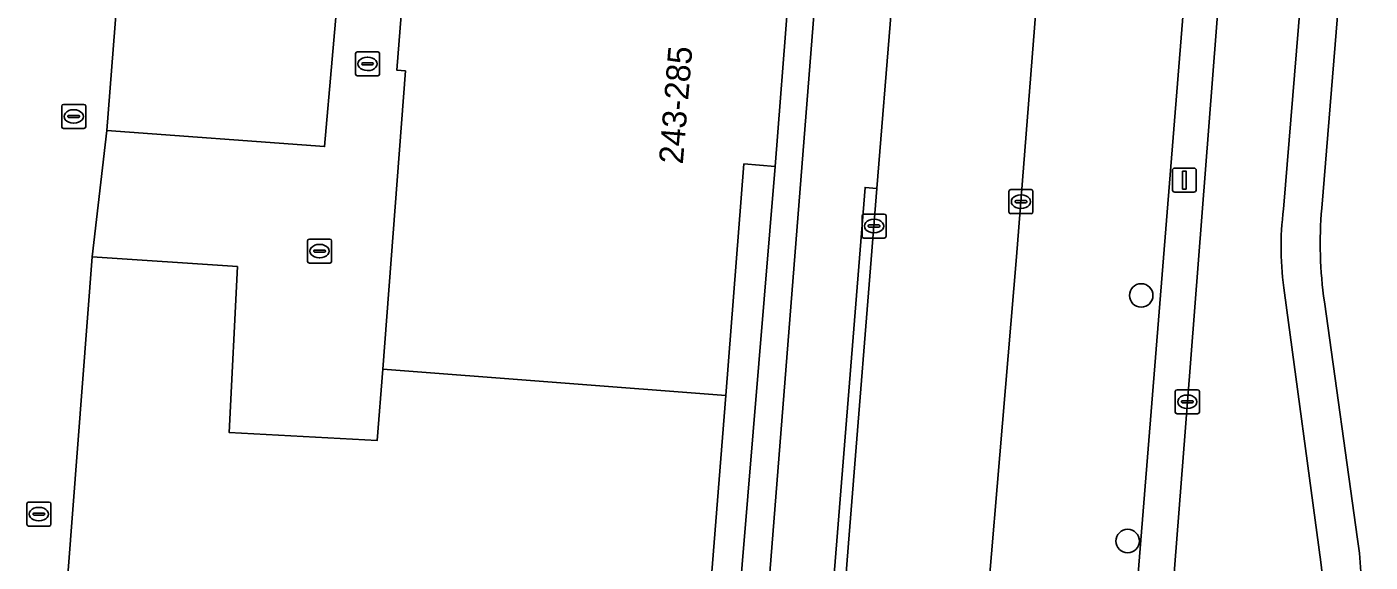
# Model space of a CAD drawing. Extents: x 160856 to 161310, y 384024 to 384878.
# Drawn here: x 161172 to 161227.9, y 384190.3 to 384212.6 of the extents above; entities that cross this region are included whole.
import ezdxf

# ---------------------------------------------------------------- set-up
doc = ezdxf.new("R2010")
doc.units = 0
for name, color, linetype in [('IMGEO_Berm_groen', 7, 'Continuous'), ('IMGEO_Boom', 7, 'Continuous'), ('IMGEO_Kolk', 7, 'Continuous'), ('IMGEO_Lichtmast', 7, 'Continuous'), ('IMGEO_Pand', 7, 'Continuous'), ('IMGEO_Pand_nummerreeks', 7, 'Continuous'), ('IMGEO_Parkeervlak_open', 7, 'Continuous'), ('IMGEO_Rijbaan_lokaal_gesloten', 7, 'Continuous'), ('IMGEO_Rijbaan_lokaal_open', 7, 'Continuous'), ('IMGEO_Voetpad_open', 7, 'Continuous')]:
    doc.layers.add(name, color=color, linetype=linetype)

msp = doc.modelspace()

# ---------------------------------------------------------------- linework, layer by layer
at = {"layer": 'IMGEO_Berm_groen'}
for points in [[(161229.529, 384268.467), (161229.449, 384267.686), (161229.325, 384266.219), (161224.3, 384204.981)], [(161225.892, 384205.014), (161231.046, 384268.295)], [(161219.187, 384267.539), (161224.271, 384267.23), (161224.48, 384267.204), (161221.069, 384224.897), (161220.682, 384220.094), (161216.321, 384165.759), (161215.782, 384159.058), (161212.885, 384159.261), (161212.995, 384161.563), (161210.036, 384161.719), (161209.719, 384161.736), (161209.242, 384156.268), (161209.155, 384155.272), (161209.068, 384154.275), (161209.373, 384154.297), (161209.267, 384152.43)], [(161218.789, 384177.498), (161220.294, 384196.951), (161221.806, 384216.321), (161223.443, 384236.712), (161224.98, 384255.032), (161225.162, 384257.276)], [(161224.34, 384201.487), (161225.848, 384190.269)], [(161227.386, 384191.221), (161226.005, 384201.112)]]:
    msp.add_lwpolyline(points, dxfattribs=at)
for centre, radius, start, end in [((161236.704, 384203.376), 12.507, 172.6261, 188.6857), ((161242.383, 384203.539), 16.557, 174.8888, 188.4288), ((161213.892, 384189.175), 13.648, 355.6, 8.6217), ((161207.617, 384187.652), 18.417, 356.4732, 8.1691)]:
    msp.add_arc(centre, radius, start, end, dxfattribs=at)
at = {"layer": 'IMGEO_Boom'}
for centre in [(161218.373, 384201.382), (161217.808, 384191.148)]:
    msp.add_circle(centre, 0.489, dxfattribs=at)
at = {"layer": 'IMGEO_Kolk'}
for p, q in [((161185.651, 384210.605), (161185.651, 384211.457)), ((161185.726, 384211.531), (161186.578, 384211.531)), ((161186.139, 384211.311), (161186.164, 384211.311)), ((161186.652, 384211.457), (161186.652, 384210.605)), ((161185.91, 384211.025), (161185.91, 384211.037)), ((161186.348, 384210.988), (161185.95, 384210.988)), ((161185.953, 384211.074), (161186.351, 384211.074)), ((161186.162, 384210.751), (161186.137, 384210.751)), ((161186.394, 384211.037), (161186.394, 384211.025)), ((161186.578, 384210.531), (161185.726, 384210.531)), ((161173.414, 384208.413), (161173.414, 384209.265)), ((161173.489, 384209.339), (161174.341, 384209.339)), ((161173.902, 384209.119), (161173.927, 384209.119)), ((161174.415, 384209.265), (161174.415, 384208.413)), ((161173.673, 384208.833), (161173.673, 384208.845)), ((161174.111, 384208.796), (161173.713, 384208.796)), ((161173.716, 384208.882), (161174.114, 384208.882)), ((161173.925, 384208.559), (161173.9, 384208.559)), ((161174.157, 384208.845), (161174.157, 384208.833)), ((161174.341, 384208.339), (161173.489, 384208.339)), ((161212.864, 384204.863), (161212.864, 384205.715)), ((161212.939, 384205.789), (161213.791, 384205.789)), ((161213.865, 384205.715), (161213.865, 384204.863)), ((161213.123, 384205.283), (161213.123, 384205.295)), ((161213.561, 384205.246), (161213.163, 384205.246)), ((161213.166, 384205.332), (161213.564, 384205.332)), ((161213.352, 384205.569), (161213.377, 384205.569)), ((161213.607, 384205.295), (161213.607, 384205.283)), ((161206.745, 384203.848), (161206.745, 384204.7)), ((161206.82, 384204.774), (161207.672, 384204.774)), ((161207.233, 384204.554), (161207.258, 384204.554)), ((161207.746, 384204.7), (161207.746, 384203.848)), ((161213.791, 384204.789), (161212.939, 384204.789)), ((161213.375, 384205.009), (161213.35, 384205.009)), ((161207.004, 384204.268), (161207.004, 384204.28)), ((161207.442, 384204.231), (161207.044, 384204.231)), ((161207.047, 384204.317), (161207.445, 384204.317)), ((161207.256, 384203.994), (161207.231, 384203.994)), ((161207.488, 384204.28), (161207.488, 384204.268)), ((161183.655, 384202.802), (161183.655, 384203.654)), ((161183.73, 384203.728), (161184.582, 384203.728)), ((161184.143, 384203.508), (161184.168, 384203.508)), ((161184.656, 384203.654), (161184.656, 384202.802)), ((161207.672, 384203.774), (161206.82, 384203.774)), ((161183.914, 384203.222), (161183.914, 384203.234)), ((161184.352, 384203.185), (161183.954, 384203.185)), ((161183.957, 384203.271), (161184.355, 384203.271)), ((161184.166, 384202.948), (161184.141, 384202.948)), ((161184.398, 384203.234), (161184.398, 384203.222)), ((161184.582, 384202.728), (161183.73, 384202.728)), ((161219.793, 384196.525), (161219.793, 384197.377)), ((161219.868, 384197.451), (161220.72, 384197.451)), ((161220.794, 384197.377), (161220.794, 384196.525)), ((161220.052, 384196.945), (161220.052, 384196.957)), ((161220.49, 384196.908), (161220.092, 384196.908)), ((161220.095, 384196.994), (161220.493, 384196.994)), ((161220.281, 384197.231), (161220.306, 384197.231)), ((161220.536, 384196.957), (161220.536, 384196.945)), ((161220.72, 384196.451), (161219.868, 384196.451)), ((161220.304, 384196.671), (161220.279, 384196.671)), ((161172.038, 384192.771), (161172.89, 384192.771)), ((161171.963, 384191.845), (161171.963, 384192.697)), ((161172.222, 384192.265), (161172.222, 384192.277)), ((161172.66, 384192.228), (161172.262, 384192.228)), ((161172.265, 384192.314), (161172.663, 384192.314)), ((161172.451, 384192.551), (161172.476, 384192.551)), ((161172.706, 384192.277), (161172.706, 384192.265)), ((161172.964, 384192.697), (161172.964, 384191.845)), ((161172.89, 384191.771), (161172.038, 384191.771)), ((161172.474, 384191.991), (161172.449, 384191.991))]:
    msp.add_line(p, q, dxfattribs=at)
for points in [[(161185.651, 384210.605), (161185.651, 384211.457)], [(161185.726, 384211.531), (161186.578, 384211.531)], [(161186.652, 384211.457), (161186.652, 384210.605)], [(161186.578, 384210.531), (161185.726, 384210.531)], [(161173.414, 384208.413), (161173.414, 384209.265)], [(161173.489, 384209.339), (161174.341, 384209.339)], [(161174.415, 384209.265), (161174.415, 384208.413)], [(161174.341, 384208.339), (161173.489, 384208.339)], [(161212.864, 384204.863), (161212.864, 384205.715)], [(161212.939, 384205.789), (161213.791, 384205.789)], [(161213.865, 384205.715), (161213.865, 384204.863)], [(161206.745, 384203.848), (161206.745, 384204.7)], [(161206.82, 384204.774), (161207.672, 384204.774)], [(161207.746, 384204.7), (161207.746, 384203.848)], [(161213.791, 384204.789), (161212.939, 384204.789)], [(161183.655, 384202.802), (161183.655, 384203.654)], [(161183.73, 384203.728), (161184.582, 384203.728)], [(161184.656, 384203.654), (161184.656, 384202.802)], [(161207.672, 384203.774), (161206.82, 384203.774)], [(161184.582, 384202.728), (161183.73, 384202.728)], [(161219.793, 384196.525), (161219.793, 384197.377)], [(161219.868, 384197.451), (161220.72, 384197.451)], [(161220.794, 384197.377), (161220.794, 384196.525)], [(161220.72, 384196.451), (161219.868, 384196.451)], [(161172.038, 384192.771), (161172.89, 384192.771)], [(161171.963, 384191.845), (161171.963, 384192.697)], [(161172.964, 384192.697), (161172.964, 384191.845)], [(161172.89, 384191.771), (161172.038, 384191.771)]]:
    msp.add_lwpolyline(points, dxfattribs=at)
for centre, radius, start, end in [((161185.728, 384211.455), 0.0765, 91.552, 178.448), ((161185.728, 384211.455), 0.0765, 91.552, 178.448), ((161186.576, 384211.455), 0.0765, 1.552, 88.448), ((161186.576, 384211.455), 0.0765, 1.552, 88.448), ((161185.95, 384211.034), 0.0403, 85.8775, 175.7526), ((161185.947, 384211.024), 0.0366, 178.938, 274.7102), ((161186.351, 384211.031), 0.043, 264.8664, 352.4533), ((161186.355, 384211.036), 0.0386, 1.7309, 96.639), ((161185.728, 384210.607), 0.0765, 181.552, 268.448), ((161185.728, 384210.607), 0.0765, 181.552, 268.448), ((161186.576, 384210.607), 0.0765, 271.552, 358.448), ((161186.576, 384210.607), 0.0765, 271.552, 358.448), ((161173.491, 384209.263), 0.0765, 91.552, 178.448), ((161173.491, 384209.263), 0.0765, 91.552, 178.448), ((161174.339, 384209.263), 0.0765, 1.552, 88.448), ((161174.339, 384209.263), 0.0765, 1.552, 88.448), ((161173.713, 384208.842), 0.0403, 85.8775, 175.7526), ((161173.71, 384208.832), 0.0366, 178.938, 274.7102), ((161174.114, 384208.839), 0.043, 264.8664, 352.4533), ((161174.118, 384208.844), 0.0386, 1.7309, 96.639), ((161173.491, 384208.415), 0.0765, 181.552, 268.448), ((161173.491, 384208.415), 0.0765, 181.552, 268.448), ((161174.339, 384208.415), 0.0765, 271.552, 358.448), ((161174.339, 384208.415), 0.0765, 271.552, 358.448), ((161212.941, 384205.713), 0.0765, 91.552, 178.448), ((161212.941, 384205.713), 0.0765, 91.552, 178.448), ((161213.789, 384205.713), 0.0765, 1.552, 88.448), ((161213.789, 384205.713), 0.0765, 1.552, 88.448), ((161213.163, 384205.292), 0.0403, 85.8775, 175.7526), ((161213.16, 384205.282), 0.0366, 178.938, 274.7102), ((161213.564, 384205.289), 0.043, 264.8664, 352.4533), ((161213.568, 384205.294), 0.0386, 1.7309, 96.639), ((161206.822, 384204.698), 0.0765, 91.552, 178.448), ((161206.822, 384204.698), 0.0765, 91.552, 178.448), ((161207.67, 384204.698), 0.0765, 1.552, 88.448), ((161207.67, 384204.698), 0.0765, 1.552, 88.448), ((161212.941, 384204.865), 0.0765, 181.552, 268.448), ((161212.941, 384204.865), 0.0765, 181.552, 268.448), ((161213.789, 384204.865), 0.0765, 271.552, 358.448), ((161213.789, 384204.865), 0.0765, 271.552, 358.448), ((161207.044, 384204.277), 0.0403, 85.8775, 175.7526), ((161207.041, 384204.267), 0.0366, 178.938, 274.7102), ((161207.445, 384204.274), 0.043, 264.8664, 352.4533), ((161207.449, 384204.279), 0.0386, 1.7309, 96.639), ((161183.732, 384203.652), 0.0765, 91.552, 178.448), ((161183.732, 384203.652), 0.0765, 91.552, 178.448), ((161184.58, 384203.652), 0.0765, 1.552, 88.448), ((161184.58, 384203.652), 0.0765, 1.552, 88.448), ((161206.822, 384203.85), 0.0765, 181.552, 268.448), ((161206.822, 384203.85), 0.0765, 181.552, 268.448), ((161207.67, 384203.85), 0.0765, 271.552, 358.448), ((161207.67, 384203.85), 0.0765, 271.552, 358.448), ((161183.954, 384203.231), 0.0403, 85.8775, 175.7526), ((161183.951, 384203.221), 0.0366, 178.938, 274.7102), ((161184.355, 384203.228), 0.043, 264.8664, 352.4533), ((161184.359, 384203.233), 0.0386, 1.7309, 96.639), ((161183.732, 384202.804), 0.0765, 181.552, 268.448), ((161183.732, 384202.804), 0.0765, 181.552, 268.448), ((161184.58, 384202.804), 0.0765, 271.552, 358.448), ((161184.58, 384202.804), 0.0765, 271.552, 358.448), ((161219.87, 384197.375), 0.0765, 91.552, 178.448), ((161219.87, 384197.375), 0.0765, 91.552, 178.448), ((161220.718, 384197.375), 0.0765, 1.552, 88.448), ((161220.718, 384197.375), 0.0765, 1.552, 88.448), ((161220.092, 384196.954), 0.0403, 85.8775, 175.7526), ((161220.089, 384196.944), 0.0366, 178.938, 274.7102), ((161220.493, 384196.951), 0.043, 264.8664, 352.4533), ((161220.497, 384196.956), 0.0386, 1.7309, 96.639), ((161219.87, 384196.527), 0.0765, 181.552, 268.448), ((161219.87, 384196.527), 0.0765, 181.552, 268.448), ((161220.718, 384196.527), 0.0765, 271.552, 358.448), ((161220.718, 384196.527), 0.0765, 271.552, 358.448), ((161172.04, 384192.695), 0.0765, 91.552, 178.448), ((161172.04, 384192.695), 0.0765, 91.552, 178.448), ((161172.888, 384192.695), 0.0765, 1.552, 88.448), ((161172.888, 384192.695), 0.0765, 1.552, 88.448), ((161172.262, 384192.274), 0.0403, 85.8775, 175.7526), ((161172.259, 384192.264), 0.0366, 178.938, 274.7102), ((161172.663, 384192.271), 0.043, 264.8664, 352.4533), ((161172.667, 384192.276), 0.0386, 1.7309, 96.639), ((161172.04, 384191.847), 0.0765, 181.552, 268.448), ((161172.04, 384191.847), 0.0765, 181.552, 268.448), ((161172.888, 384191.847), 0.0765, 271.552, 358.448), ((161172.888, 384191.847), 0.0765, 271.552, 358.448)]:
    msp.add_arc(centre, radius, start, end, dxfattribs=at)
for centre, major_axis, ratio, start_param, end_param in [((161186.138, 384211.031), (-0.387, 0.002), 0.722429, 4.712389, 7.853982), ((161186.163, 384211.031), (-0.39, 0.002), 0.717154, 1.570796, 4.712389), ((161173.901, 384208.839), (-0.387, 0.002), 0.722429, 4.712389, 7.853982), ((161173.926, 384208.839), (-0.39, 0.002), 0.717154, 1.570796, 4.712389), ((161213.351, 384205.289), (-0.387, 0.002), 0.722429, 4.712389, 7.853982), ((161213.376, 384205.289), (-0.39, 0.002), 0.717154, 1.570796, 4.712389), ((161207.232, 384204.274), (-0.387, 0.002), 0.722429, 4.712389, 7.853982), ((161207.257, 384204.274), (-0.39, 0.002), 0.717154, 1.570796, 4.712389), ((161184.142, 384203.228), (-0.387, 0.002), 0.722429, 4.712389, 7.853982), ((161184.167, 384203.228), (-0.39, 0.002), 0.717154, 1.570796, 4.712389), ((161220.28, 384196.951), (-0.387, 0.002), 0.722429, 4.712389, 7.853982), ((161220.305, 384196.951), (-0.39, 0.002), 0.717154, 1.570796, 4.712389), ((161172.45, 384192.271), (-0.387, 0.002), 0.722429, 4.712389, 7.853982), ((161172.475, 384192.271), (-0.39, 0.002), 0.717154, 1.570796, 4.712389)]:
    msp.add_ellipse(centre, major_axis=major_axis, ratio=ratio, start_param=start_param, end_param=end_param, dxfattribs=at)
at = {"layer": 'IMGEO_Lichtmast'}
for p, q in [((161219.674, 384205.79), (161219.674, 384206.59)), ((161219.674, 384206.59), (161219.674, 384205.79)), ((161219.774, 384206.69), (161220.564, 384206.69)), ((161220.564, 384206.69), (161219.774, 384206.69)), ((161220.664, 384206.59), (161220.664, 384205.79)), ((161220.664, 384205.79), (161220.664, 384206.59)), ((161220.564, 384205.69), (161219.774, 384205.69)), ((161219.774, 384205.69), (161220.564, 384205.69))]:
    msp.add_line(p, q, dxfattribs=at)
msp.add_lwpolyline([(161220.094, 384206.565), (161220.244, 384206.565), (161220.244, 384205.815), (161220.094, 384205.815), (161220.094, 384206.565)], dxfattribs=at)
for centre, start, end in [((161219.774, 384206.59), 90, 180), ((161219.774, 384206.59), 90, 180), ((161220.564, 384206.59), 0, 90), ((161220.564, 384206.59), 360, 90), ((161219.774, 384205.79), 180, 270), ((161219.774, 384205.79), 180, 270), ((161220.564, 384205.79), 270, 0), ((161220.564, 384205.79), 270, 0)]:
    msp.add_arc(centre, 0.1, start, end, dxfattribs=at)
at = {"layer": 'IMGEO_Pand'}
for points in [[(161203.203, 384223.59), (161188.899, 384224.73), (161188.639, 384221.473), (161182.557, 384222.022), (161182.954, 384228.921), (161176.935, 384229.242), (161175.287, 384208.253), (161184.366, 384207.582), (161185.004, 384214.874), (161187.682, 384214.656), (161187.366, 384210.77), (161187.732, 384210.74), (161186.782, 384198.313), (161201.069, 384197.213), (161201.826, 384206.859), (161203.125, 384206.757), (161203.674, 384213.741), (161202.438, 384213.838)], [(161184.731, 384172.149), (161198.917, 384170.976), (161199.672, 384180.591), (161200.976, 384180.488), (161201.526, 384187.487), (161200.313, 384187.582), (161201.069, 384197.213), (161186.782, 384198.313), (161186.554, 384195.339), (161180.383, 384195.672), (161180.729, 384202.583), (161174.685, 384202.993), (161173.075, 384181.94), (161182.383, 384181.193), (161183.033, 384188.524), (161185.711, 384188.306), (161185.395, 384184.42), (161185.743, 384184.392)]]:
    msp.add_lwpolyline(points, close=True, dxfattribs=at)
at = {"layer": 'IMGEO_Parkeervlak_open'}
msp.add_lwpolyline([(161211.316, 384166.088), (161213.293, 384165.943), (161216.321, 384165.759), (161220.682, 384220.094), (161215.005, 384220.471), (161214.614, 384220.697), (161214.599, 384220.777), (161214.585, 384220.857), (161213.184, 384202.99), (161211.337, 384181.045), (161209.815, 384162.885), (161209.721, 384161.764), (161209.719, 384161.736), (161210.036, 384161.719), (161210.12, 384163.699), (161210.247, 384165.145)], dxfattribs=at)
at = {"layer": 'IMGEO_Rijbaan_lokaal_gesloten'}
for points in [[(161224.3, 384204.981), (161229.325, 384266.219), (161229.449, 384267.686), (161229.529, 384268.467)], [(161231.046, 384268.295), (161225.892, 384205.014)], [(161225.162, 384257.276), (161224.98, 384255.032), (161223.443, 384236.712), (161221.806, 384216.321), (161220.294, 384196.951), (161218.789, 384177.498)], [(161225.848, 384190.269), (161224.34, 384201.487)], [(161226.005, 384201.112), (161227.386, 384191.221)]]:
    msp.add_lwpolyline(points, dxfattribs=at)
for centre, radius, start, end in [((161236.704, 384203.376), 12.507, 172.6261, 188.6857), ((161242.383, 384203.539), 16.557, 174.8888, 188.4288), ((161213.892, 384189.175), 13.648, 355.6, 8.6217), ((161207.617, 384187.652), 18.417, 356.4732, 8.1691)]:
    msp.add_arc(centre, radius, start, end, dxfattribs=at)
at = {"layer": 'IMGEO_Rijbaan_lokaal_open'}
for points in [[(161215.05, 384278.021), (161215.074, 384278.391), (161213.24, 384278.519), (161213.121, 384277.179), (161212.035, 384265.52), (161212.02, 384265.357), (161211.753, 384262.446), (161211.187, 384253.691), (161211.133, 384253.071), (161210.868, 384250), (161210.029, 384239.243), (161209.635, 384234.186), (161209.458, 384231.971), (161207.958, 384213.205), (161207.369, 384205.837), (161206.188, 384191.059), (161205.858, 384186.962)], [(161173.075, 384181.94), (161174.685, 384202.993), (161175.287, 384208.253), (161176.935, 384229.242), (161177.27, 384234.565), (161178.514, 384250), (161178.951, 384255.419)], [(161209.719, 384161.736), (161209.721, 384161.764), (161209.815, 384162.885), (161211.337, 384181.045), (161213.184, 384202.99), (161214.585, 384220.857)]]:
    msp.add_lwpolyline(points, dxfattribs=at)
msp.add_lwpolyline([(161174.685, 384202.993), (161180.729, 384202.583), (161180.383, 384195.672), (161186.554, 384195.339), (161186.782, 384198.313), (161187.732, 384210.74), (161187.366, 384210.77), (161187.682, 384214.656), (161185.004, 384214.874), (161184.366, 384207.582), (161175.287, 384208.253)], close=True, dxfattribs=at)
at = {"layer": 'IMGEO_Voetpad_open'}
for points in [[(161213.121, 384277.179), (161213.24, 384278.519), (161213.412, 384280.458), (161209.303, 384280.318), (161204.911, 384280.464), (161204.963, 384277.713), (161205.02, 384274.053), (161205.145, 384265.777), (161205.289, 384259.645), (161204.63, 384259.631), (161204.244, 384253.556), (161205.595, 384253.449), (161206.896, 384253.371), (161207.915, 384253.294), (161207.655, 384250), (161197.483, 384121.051)], [(161205.36, 384187.005), (161206.871, 384205.88), (161207.369, 384205.837), (161207.958, 384213.205), (161207.46, 384213.247), (161208.96, 384232.013), (161209.458, 384231.971), (161209.635, 384234.186), (161210.029, 384239.243), (161209.531, 384239.284), (161210.386, 384250), (161210.635, 384253.113)]]:
    msp.add_lwpolyline(points, dxfattribs=at)
for points in [[(161207.655, 384250), (161207.915, 384253.294), (161206.896, 384253.371), (161206.594, 384250), (161205.72, 384240.225), (161205.172, 384233.241), (161203.674, 384213.741), (161203.125, 384206.757), (161201.526, 384187.487), (161200.976, 384180.488), (161199.379, 384161.266), (161198.825, 384154.208), (161197.28, 384134.771), (161196.728, 384127.745), (161196.213, 384121.151), (161197.483, 384121.051)], [(161201.526, 384187.487), (161203.125, 384206.757), (161201.826, 384206.859), (161201.069, 384197.213), (161200.313, 384187.582)], [(161207.369, 384205.837), (161206.871, 384205.88), (161205.36, 384187.005), (161205.858, 384186.962), (161206.188, 384191.059)]]:
    msp.add_lwpolyline(points, close=True, dxfattribs=at)

# ---------------------------------------------------------------- texts
at = {"layer": 'IMGEO_Pand_nummerreeks'}
msp.add_text('243-285', height=1, rotation=85.2765, dxfattribs=at).set_placement((161199.281, 384206.831))

doc.saveas('drawing.dxf')
